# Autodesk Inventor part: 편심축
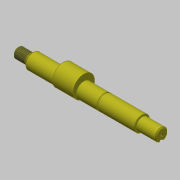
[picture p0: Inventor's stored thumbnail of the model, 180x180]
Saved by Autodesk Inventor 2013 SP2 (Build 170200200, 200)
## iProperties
Created: 2016-08
Part Number: 편심축
Material: 강철, 탄소
Document SubType Name: Modeling
Designer: mduedu
Density: 7.87 g/cm^3
Author: mduedu
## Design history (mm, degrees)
sketch "스케치1"
  geometry: L1 (-70, 0)-(70, 0); L2 (-70, 0)-(-70, 5); L3 (-70, 5)-(-56, 5); L4 (-56, 5)-(-56, 7.5); L5 (-56, 7.5)-(51, 7.5); L6 (51, 7.5)-(51, 6); L7 (51, 6)-(70, 6); L8 (70, 6)-(70, 0); 2 further points
  constraints: 16 end point, 5 parallel, 2 perpendicular, 1 coincident, 1 horizontal, 1 midpoint
  dimensions: "d0" = 140 distance of L1.start L1.end; "d2" = 14 distance of L2.end L3.end; "d3" = 19 distance of L6.end L7.end; "d4" = 10 diameter of L3 L1; "d5" = 15 diameter of L5 L1; "d6" = 12 diameter of L7 L1
revolve "회전1" sketch "스케치1" stored, may be unused: angle "d7" = 90 deg
sketch "스케치2"
  geometry: L1 (-56, -5)-(-56, 5) reference; L2 (70, -6)-(70, 6) reference; L3 (-56, 0)-(70, 0); L4 (-58, 4.5)-(-58, 5); L5 (-58, 5)-(-56, 5); L6 (-56, 5)-(-56, 4.5); L7 (-58, 4.5)-(-56, 4.5); 1 further point
  constraints: 10 end point, 2 midpoint, 1 parallel, 1 perpendicular, 1 point on line
  dimensions: "d8" = 2 distance of L4.end L5.end; "d10" = 10 diameter of L5 L3; "d11" = 9 diameter of L7 L3
revolve "회전2" sketch "스케치2" stored, may be unused: angle "d12" = 90 deg
node "작업 평면1"
sketch "스케치3"
  geometry: C1 r 10.5 at (0, 3); C2 r 7.5 at (0, 0) reference; 1 further point
  constraints: 1 centre point, 1 tangent, 1 vertical alignment
  dimensions: "d14" = 3 distance of C1.centre point (0, 0); "d15" = 21 diameter of C1 (derived)
extrude "돌출1" join sketch "스케치3" distance "d16" = 20; taper "d17" = 0 deg
sketch "스케치5"
  geometry: L1 (-70, -5)-(-70, 5) reference; L2 (70, -6)-(70, 6) reference; L3 (-70, 0)-(70, 0); L4 (-6, 7.5)-(51, 7.5) reference; L5 (15.15, 7.5)-(14, 7.5); L6 (14, 7.5)-(14, 7.15); L7 (14, 7.15)-(15.15, 7.15); L8 (15.15, 7.15)-(15.15, 7.5); 1 further point
  constraints: 10 end point, 2 midpoint, 2 parallel, 1 horizontal, 1 perpendicular, 1 point on line
  dimensions: "d19" = 56 distance between parallel lines of L6 L2; "d20" = 1.15 distance between parallel lines of L8 L6; "d21" = 14.3 diameter of L7 L3
revolve "회전3" sketch "스케치5" stored, may be unused: angle "d22" = 90 deg
node "작업 평면3"
sketch "스케치6"
  geometry: L1 (9.5, 7.5)-(9.5, -7.5) reference; L2 (7.5, 2)-(-9.5, 2); L3 (-9.5, 2)-(-9.5, -2); L4 (-9.5, -2)-(7.5, -2); L5 (-9.5, 6)-(-9.5, -6) reference; A1 r 2 centre (7.5, 0) between (7.5, -2) and (7.5, 2); 2 further points
  constraints: 6 end point, 3 tangent, 2 midpoint, 2 point on circle, 1 centre point, 1 horizontal, 1 horizontal alignment, 1 parallel, 1 perpendicular
  dimensions: "d23" = 4 distance between parallel lines of L4 L2
extrude "돌출2" cut sketch "스케치6" distance "d25" = 2.5; taper "d26" = 0 deg
feature "스레드1" dims "d27" = 10, "d28" = 0
chamfer "모따기5" distance "d41" = 0.5; stored, may be unused: second distance "d42" = 2, angle "d43" = 45 deg
chamfer "모따기6" distance "d44" = 0.5; stored, may be unused: second distance "d45" = 2, angle "d46" = 45 deg
chamfer "모따기7" distance "d47" = 1; stored, may be unused: second distance "d48" = 2, angle "d49" = 45 deg
chamfer "모따기8" distance "d50" = 1; stored, may be unused: second distance "d51" = 2, angle "d52" = 45 deg
sketch "스케치8"
  geometry: 1 further point
hole "구멍1" sketch "스케치8" at (2, 3.5) diameter "d53" = 3.242; stored, may be unused: countersink angle "d57" = 90 deg, drill point angle "d59" = 120 deg; dims "d54" = 10, "d55" = 4, "d56" = 2, "d58" = 12
node "솔리드1"
other parameters: "d13" = -44
